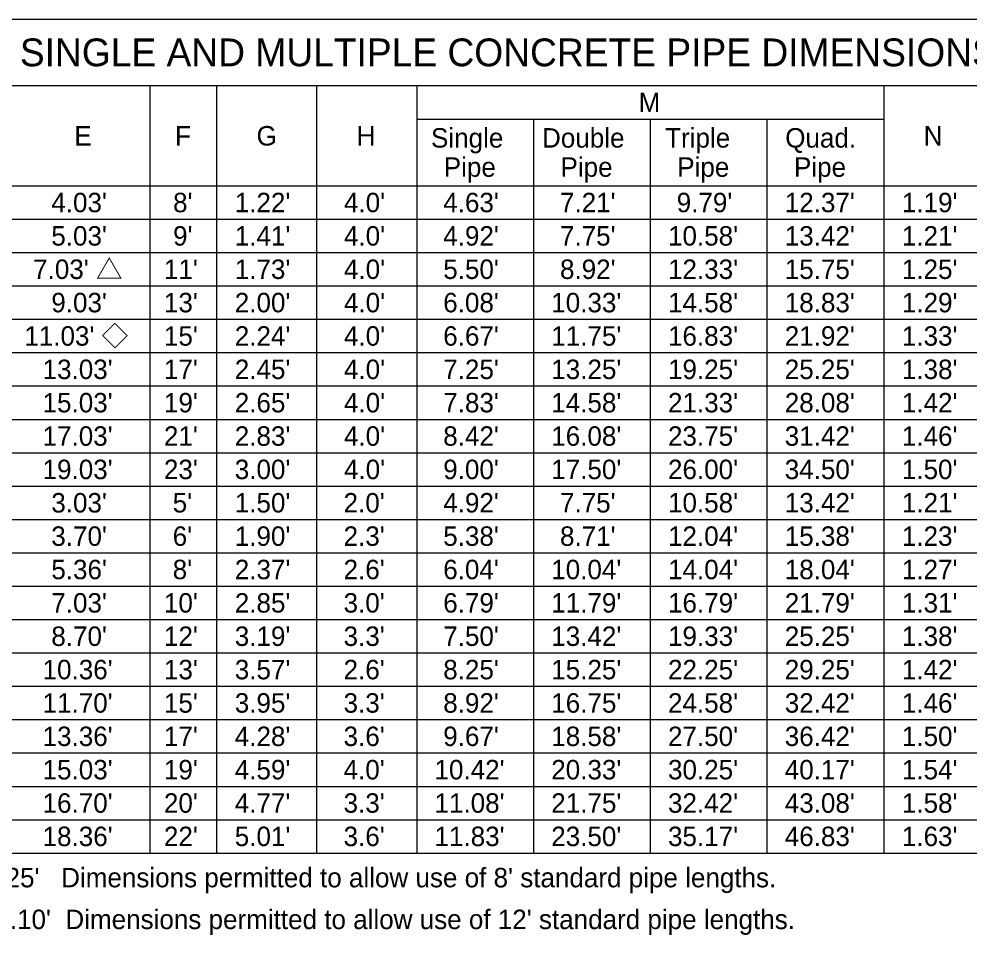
# Model space of a CAD drawing. Extents: x 2 to 14.5, y 0.1 to 8.2.
# Drawn here: x 4.889 to 8.31, y 4.933 to 8.227 of the extents above; entities that cross this region are included whole.
import ezdxf

# ---------------------------------------------------------------- set-up
doc = ezdxf.new("R2010")
doc.units = 0
doc.layers.add('TextNotes', color=7, linetype='Continuous')
doc.layers.add('TextTables', color=7, linetype='Continuous')

msp = doc.modelspace()

# ---------------------------------------------------------------- linework, layer by layer
at = {"layer": 'TextTables'}
msp.add_line((2, 8.2274), (13.4, 8.2274), dxfattribs=at)
for points in [[(13.4, 7.9874), (11.72, 7.9874), (10.04, 7.9874), (8.36, 7.9874), (8, 7.9874), (6.32, 7.9874), (5.96, 7.9874), (5.6, 7.9874), (5.36, 7.9874), (4.88, 7.9874), (4.46, 7.9874), (3.98, 7.9874), (3.56, 7.9874), (3.14, 7.9874), (2.84, 7.9874), (2.54, 7.9874), (2.24, 7.9874), (2, 7.9874)], [(5.36, 7.9874), (5.36, 7.6274), (5.36, 7.5074), (5.36, 7.3874), (5.36, 7.2674), (5.36, 7.1474), (5.36, 7.0274), (5.36, 6.9074), (5.36, 6.7874), (5.36, 6.6674), (5.36, 6.5474), (5.36, 6.4274), (5.36, 6.3074), (5.36, 6.1874), (5.36, 6.0674), (5.36, 5.9474), (5.36, 5.8274), (5.36, 5.7074), (5.36, 5.5874), (5.36, 5.4674), (5.36, 5.3474), (5.36, 5.2274)], [(5.6, 7.9874), (5.6, 7.6274), (5.6, 7.5074), (5.6, 7.3874), (5.6, 7.2674), (5.6, 7.1474), (5.6, 7.0274), (5.6, 6.9074), (5.6, 6.7874), (5.6, 6.6674), (5.6, 6.5474), (5.6, 6.4274), (5.6, 6.3074), (5.6, 6.1874), (5.6, 6.0674), (5.6, 5.9474), (5.6, 5.8274), (5.6, 5.7074), (5.6, 5.5874), (5.6, 5.4674), (5.6, 5.3474), (5.6, 5.2274)], [(5.96, 7.9874), (5.96, 7.6274), (5.96, 7.5074), (5.96, 7.3874), (5.96, 7.2674), (5.96, 7.1474), (5.96, 7.0274), (5.96, 6.9074), (5.96, 6.7874), (5.96, 6.6674), (5.96, 6.5474), (5.96, 6.4274), (5.96, 6.3074), (5.96, 6.1874), (5.96, 6.0674), (5.96, 5.9474), (5.96, 5.8274), (5.96, 5.7074), (5.96, 5.5874), (5.96, 5.4674), (5.96, 5.3474), (5.96, 5.2274)], [(6.32, 7.9874), (6.32, 7.8674), (6.32, 7.6274), (6.32, 7.5074), (6.32, 7.3874), (6.32, 7.2674), (6.32, 7.1474), (6.32, 7.0274), (6.32, 6.9074), (6.32, 6.7874), (6.32, 6.6674), (6.32, 6.5474), (6.32, 6.4274), (6.32, 6.3074), (6.32, 6.1874), (6.32, 6.0674), (6.32, 5.9474), (6.32, 5.8274), (6.32, 5.7074), (6.32, 5.5874), (6.32, 5.4674), (6.32, 5.3474), (6.32, 5.2274)], [(8, 7.9874), (8, 7.8674), (8, 7.6274), (8, 7.5074), (8, 7.3874), (8, 7.2674), (8, 7.1474), (8, 7.0274), (8, 6.9074), (8, 6.7874), (8, 6.6674), (8, 6.5474), (8, 6.4274), (8, 6.3074), (8, 6.1874), (8, 6.0674), (8, 5.9474), (8, 5.8274), (8, 5.7074), (8, 5.5874), (8, 5.4674), (8, 5.3474), (8, 5.2274)], [(6.32, 7.8674), (6.74, 7.8674), (7.16, 7.8674), (7.58, 7.8674), (8, 7.8674)], [(6.74, 7.8674), (6.74, 7.6274), (6.74, 7.5074), (6.74, 7.3874), (6.74, 7.2674), (6.74, 7.1474), (6.74, 7.0274), (6.74, 6.9074), (6.74, 6.7874), (6.74, 6.6674), (6.74, 6.5474), (6.74, 6.4274), (6.74, 6.3074), (6.74, 6.1874), (6.74, 6.0674), (6.74, 5.9474), (6.74, 5.8274), (6.74, 5.7074), (6.74, 5.5874), (6.74, 5.4674), (6.74, 5.3474), (6.74, 5.2274)], [(7.16, 7.8674), (7.16, 7.6274), (7.16, 7.5074), (7.16, 7.3874), (7.16, 7.2674), (7.16, 7.1474), (7.16, 7.0274), (7.16, 6.9074), (7.16, 6.7874), (7.16, 6.6674), (7.16, 6.5474), (7.16, 6.4274), (7.16, 6.3074), (7.16, 6.1874), (7.16, 6.0674), (7.16, 5.9474), (7.16, 5.8274), (7.16, 5.7074), (7.16, 5.5874), (7.16, 5.4674), (7.16, 5.3474), (7.16, 5.2274)], [(7.58, 7.8674), (7.58, 7.6274), (7.58, 7.5074), (7.58, 7.3874), (7.58, 7.2674), (7.58, 7.1474), (7.58, 7.0274), (7.58, 6.9074), (7.58, 6.7874), (7.58, 6.6674), (7.58, 6.5474), (7.58, 6.4274), (7.58, 6.3074), (7.58, 6.1874), (7.58, 6.0674), (7.58, 5.9474), (7.58, 5.8274), (7.58, 5.7074), (7.58, 5.5874), (7.58, 5.4674), (7.58, 5.3474), (7.58, 5.2274)], [(2, 7.6274), (2.24, 7.6274), (2.54, 7.6274), (2.84, 7.6274), (3.14, 7.6274), (3.56, 7.6274), (3.98, 7.6274), (4.46, 7.6274), (4.88, 7.6274), (5.36, 7.6274), (5.6, 7.6274), (5.96, 7.6274), (6.32, 7.6274), (6.74, 7.6274), (7.16, 7.6274), (7.58, 7.6274), (8, 7.6274), (8.36, 7.6274)], [(2.24, 7.5074), (2.54, 7.5074), (2.84, 7.5074), (3.14, 7.5074), (3.56, 7.5074), (3.98, 7.5074), (4.46, 7.5074), (4.88, 7.5074), (5.36, 7.5074), (5.6, 7.5074), (5.96, 7.5074), (6.32, 7.5074), (6.74, 7.5074), (7.16, 7.5074), (7.58, 7.5074), (8, 7.5074), (8.36, 7.5074)], [(2.24, 7.3874), (2.54, 7.3874), (2.84, 7.3874), (3.14, 7.3874), (3.56, 7.3874), (3.98, 7.3874), (4.46, 7.3874), (4.88, 7.3874), (5.36, 7.3874), (5.6, 7.3874), (5.96, 7.3874), (6.32, 7.3874), (6.74, 7.3874), (7.16, 7.3874), (7.58, 7.3874), (8, 7.3874), (8.36, 7.3874)], [(2.24, 7.2674), (2.54, 7.2674), (2.84, 7.2674), (3.14, 7.2674), (3.56, 7.2674), (3.98, 7.2674), (4.46, 7.2674), (4.88, 7.2674), (5.36, 7.2674), (5.6, 7.2674), (5.96, 7.2674), (6.32, 7.2674), (6.74, 7.2674), (7.16, 7.2674), (7.58, 7.2674), (8, 7.2674), (8.36, 7.2674)], [(2.24, 7.1474), (2.54, 7.1474), (2.84, 7.1474), (3.14, 7.1474), (3.56, 7.1474), (3.98, 7.1474), (4.46, 7.1474), (4.88, 7.1474), (5.36, 7.1474), (5.6, 7.1474), (5.96, 7.1474), (6.32, 7.1474), (6.74, 7.1474), (7.16, 7.1474), (7.58, 7.1474), (8, 7.1474), (8.36, 7.1474)], [(2.24, 7.0274), (2.54, 7.0274), (2.84, 7.0274), (3.14, 7.0274), (3.56, 7.0274), (3.98, 7.0274), (4.46, 7.0274), (4.88, 7.0274), (5.36, 7.0274), (5.6, 7.0274), (5.96, 7.0274), (6.32, 7.0274), (6.74, 7.0274), (7.16, 7.0274), (7.58, 7.0274), (8, 7.0274), (8.36, 7.0274)], [(2.24, 6.9074), (2.54, 6.9074), (2.84, 6.9074), (3.14, 6.9074), (3.56, 6.9074), (3.98, 6.9074), (4.46, 6.9074), (4.88, 6.9074), (5.36, 6.9074), (5.6, 6.9074), (5.96, 6.9074), (6.32, 6.9074), (6.74, 6.9074), (7.16, 6.9074), (7.58, 6.9074), (8, 6.9074), (8.36, 6.9074)], [(2.24, 6.7874), (2.54, 6.7874), (2.84, 6.7874), (3.14, 6.7874), (3.56, 6.7874), (3.98, 6.7874), (4.46, 6.7874), (4.88, 6.7874), (5.36, 6.7874), (5.6, 6.7874), (5.96, 6.7874), (6.32, 6.7874), (6.74, 6.7874), (7.16, 6.7874), (7.58, 6.7874), (8, 6.7874), (8.36, 6.7874)], [(2.24, 6.6674), (2.54, 6.6674), (2.84, 6.6674), (3.14, 6.6674), (3.56, 6.6674), (3.98, 6.6674), (4.46, 6.6674), (4.88, 6.6674), (5.36, 6.6674), (5.6, 6.6674), (5.96, 6.6674), (6.32, 6.6674), (6.74, 6.6674), (7.16, 6.6674), (7.58, 6.6674), (8, 6.6674), (8.36, 6.6674)], [(2, 6.5474), (2.24, 6.5474), (2.54, 6.5474), (2.84, 6.5474), (3.14, 6.5474), (3.56, 6.5474), (3.98, 6.5474), (4.46, 6.5474), (4.88, 6.5474), (5.36, 6.5474), (5.6, 6.5474), (5.96, 6.5474), (6.32, 6.5474), (6.74, 6.5474), (7.16, 6.5474), (7.58, 6.5474), (8, 6.5474), (8.36, 6.5474)], [(2.24, 6.4274), (2.54, 6.4274), (2.84, 6.4274), (3.14, 6.4274), (3.56, 6.4274), (3.98, 6.4274), (4.46, 6.4274), (4.88, 6.4274), (5.36, 6.4274), (5.6, 6.4274), (5.96, 6.4274), (6.32, 6.4274), (6.74, 6.4274), (7.16, 6.4274), (7.58, 6.4274), (8, 6.4274), (8.36, 6.4274)], [(2.24, 6.3074), (2.54, 6.3074), (2.84, 6.3074), (3.14, 6.3074), (3.56, 6.3074), (3.98, 6.3074), (4.46, 6.3074), (4.88, 6.3074), (5.36, 6.3074), (5.6, 6.3074), (5.96, 6.3074), (6.32, 6.3074), (6.74, 6.3074), (7.16, 6.3074), (7.58, 6.3074), (8, 6.3074), (8.36, 6.3074)], [(2.24, 6.1874), (2.54, 6.1874), (2.84, 6.1874), (3.14, 6.1874), (3.56, 6.1874), (3.98, 6.1874), (4.46, 6.1874), (4.88, 6.1874), (5.36, 6.1874), (5.6, 6.1874), (5.96, 6.1874), (6.32, 6.1874), (6.74, 6.1874), (7.16, 6.1874), (7.58, 6.1874), (8, 6.1874), (8.36, 6.1874)], [(2.24, 6.0674), (2.54, 6.0674), (2.84, 6.0674), (3.14, 6.0674), (3.56, 6.0674), (3.98, 6.0674), (4.46, 6.0674), (4.88, 6.0674), (5.36, 6.0674), (5.6, 6.0674), (5.96, 6.0674), (6.32, 6.0674), (6.74, 6.0674), (7.16, 6.0674), (7.58, 6.0674), (8, 6.0674), (8.36, 6.0674)], [(2.24, 5.9474), (2.54, 5.9474), (2.84, 5.9474), (3.14, 5.9474), (3.56, 5.9474), (3.98, 5.9474), (4.46, 5.9474), (4.88, 5.9474), (5.36, 5.9474), (5.6, 5.9474), (5.96, 5.9474), (6.32, 5.9474), (6.74, 5.9474), (7.16, 5.9474), (7.58, 5.9474), (8, 5.9474), (8.36, 5.9474)], [(2.24, 5.8274), (2.54, 5.8274), (2.84, 5.8274), (3.14, 5.8274), (3.56, 5.8274), (3.98, 5.8274), (4.46, 5.8274), (4.88, 5.8274), (5.36, 5.8274), (5.6, 5.8274), (5.96, 5.8274), (6.32, 5.8274), (6.74, 5.8274), (7.16, 5.8274), (7.58, 5.8274), (8, 5.8274), (8.36, 5.8274)], [(2.24, 5.7074), (2.54, 5.7074), (2.84, 5.7074), (3.14, 5.7074), (3.56, 5.7074), (3.98, 5.7074), (4.46, 5.7074), (4.88, 5.7074), (5.36, 5.7074), (5.6, 5.7074), (5.96, 5.7074), (6.32, 5.7074), (6.74, 5.7074), (7.16, 5.7074), (7.58, 5.7074), (8, 5.7074), (8.36, 5.7074)], [(2.24, 5.5874), (2.54, 5.5874), (2.84, 5.5874), (3.14, 5.5874), (3.56, 5.5874), (3.98, 5.5874), (4.46, 5.5874), (4.88, 5.5874), (5.36, 5.5874), (5.6, 5.5874), (5.96, 5.5874), (6.32, 5.5874), (6.74, 5.5874), (7.16, 5.5874), (7.58, 5.5874), (8, 5.5874), (8.36, 5.5874)], [(2.24, 5.4674), (2.54, 5.4674), (2.84, 5.4674), (3.14, 5.4674), (3.56, 5.4674), (3.98, 5.4674), (4.46, 5.4674), (4.88, 5.4674), (5.36, 5.4674), (5.6, 5.4674), (5.96, 5.4674), (6.32, 5.4674), (6.74, 5.4674), (7.16, 5.4674), (7.58, 5.4674), (8, 5.4674), (8.36, 5.4674)], [(2.24, 5.3474), (2.54, 5.3474), (2.84, 5.3474), (3.14, 5.3474), (3.56, 5.3474), (3.98, 5.3474), (4.46, 5.3474), (4.88, 5.3474), (5.36, 5.3474), (5.6, 5.3474), (5.96, 5.3474), (6.32, 5.3474), (6.74, 5.3474), (7.16, 5.3474), (7.58, 5.3474), (8, 5.3474), (8.36, 5.3474)], [(2, 5.2274), (2.24, 5.2274), (2.54, 5.2274), (2.84, 5.2274), (3.14, 5.2274), (3.56, 5.2274), (3.98, 5.2274), (4.46, 5.2274), (4.88, 5.2274), (5.36, 5.2274), (5.6, 5.2274), (5.96, 5.2274), (6.32, 5.2274), (6.74, 5.2274), (7.16, 5.2274), (7.58, 5.2274), (8, 5.2274), (8.36, 5.2274)]]:
    msp.add_lwpolyline(points, dxfattribs=at)

# ---------------------------------------------------------------- texts
at = {"layer": 'TextNotes'}
for s, height, p in [('SINGLE AND MULTIPLE CONCRETE PIPE DIMENSIONS AND QUANTITIES', 0.1, (4.8923, 8.0574)), ('M', 0.07, (7.1183, 7.8924)), ('E', 0.07, (5.0882, 7.7724)), ('F', 0.07, (5.4503, 7.7724)), ('G', 0.07, (5.7438, 7.7724)), ('H', 0.07, (6.1037, 7.7724)), ('Single', 0.07, (6.3714, 7.7649)), ('Double', 0.07, (6.7709, 7.7649)), ('Triple', 0.07, (7.2137, 7.7649)), ('Quad.', 0.07, (7.6457, 7.7649)), ('N', 0.07, (8.1438, 7.7724)), ('Pipe', 0.07, (6.4173, 7.6599)), ('Pipe', 0.07, (6.8373, 7.6599)), ('Pipe', 0.07, (7.2573, 7.6599)), ('Pipe', 0.07, (7.6773, 7.6599))]:
    msp.add_text(s, height=height, dxfattribs=at).set_placement(p)
for s, p in [("4.03'", (5.0054, 7.5324)), (" 8'", (5.4175, 7.5324)), ("1.22'", (5.6654, 7.5324)), (" 4.0'", (6.0323, 7.5324)), ("4.63'", (6.4154, 7.5324)), ("7.21'", (6.8354, 7.5324)), ("9.79'", (7.2554, 7.5324)), ("12.37'", (7.644, 7.5324)), ("1.19'", (8.0654, 7.5324)), ("5.03'", (5.0054, 7.4124)), (" 9'", (5.4175, 7.4124)), ("1.41'", (5.6654, 7.4124)), (" 4.0'", (6.0323, 7.4124)), ("4.92'", (6.4154, 7.4124)), ("7.75'", (6.8354, 7.4124)), ("10.58'", (7.224, 7.4124)), ("13.42'", (7.644, 7.4124)), ("1.21'", (8.0654, 7.4124)), ("7.03' △", (4.94, 7.2924)), ("11'", (5.4106, 7.2924)), ("1.73'", (5.6654, 7.2924)), (" 4.0'", (6.0323, 7.2924)), ("5.50'", (6.4154, 7.2924)), ("8.92'", (6.8354, 7.2924)), ("12.33'", (7.224, 7.2924)), ("15.75'", (7.644, 7.2924)), ("1.25'", (8.0654, 7.2924)), ("9.03'", (5.0054, 7.1724)), ("13'", (5.4106, 7.1724)), ("2.00'", (5.6654, 7.1724)), (" 4.0'", (6.0323, 7.1724)), ("6.08'", (6.4154, 7.1724)), ("10.33'", (6.804, 7.1724)), ("14.58'", (7.224, 7.1724)), ("18.83'", (7.644, 7.1724)), ("1.29'", (8.0654, 7.1724)), ("11.03' ◇", (4.9083, 7.0524)), ("15'", (5.4106, 7.0524)), ("2.24'", (5.6654, 7.0524)), (" 4.0'", (6.0323, 7.0524)), ("6.67'", (6.4154, 7.0524)), ("11.75'", (6.804, 7.0524)), ("16.83'", (7.224, 7.0524)), ("21.92'", (7.644, 7.0524)), ("1.33'", (8.0654, 7.0524)), ("13.03'", (4.974, 6.9324)), ("17'", (5.4106, 6.9324)), ("2.45'", (5.6654, 6.9324)), (" 4.0'", (6.0323, 6.9324)), ("7.25'", (6.4154, 6.9324)), ("13.25'", (6.804, 6.9324)), ("19.25'", (7.224, 6.9324)), ("25.25'", (7.644, 6.9324)), ("1.38'", (8.0654, 6.9324)), ("15.03'", (4.974, 6.8124)), ("19'", (5.4106, 6.8124)), ("2.65'", (5.6654, 6.8124)), (" 4.0'", (6.0323, 6.8124)), ("7.83'", (6.4154, 6.8124)), ("14.58'", (6.804, 6.8124)), ("21.33'", (7.224, 6.8124)), ("28.08'", (7.644, 6.8124)), ("1.42'", (8.0654, 6.8124)), ("17.03'", (4.974, 6.6924)), ("21'", (5.4106, 6.6924)), ("2.83'", (5.6654, 6.6924)), (" 4.0'", (6.0323, 6.6924)), ("8.42'", (6.4154, 6.6924)), ("16.08'", (6.804, 6.6924)), ("23.75'", (7.224, 6.6924)), ("31.42'", (7.644, 6.6924)), ("1.46'", (8.0654, 6.6924)), ("19.03'", (4.974, 6.5724)), ("23'", (5.4106, 6.5724)), ("3.00'", (5.6654, 6.5724)), (" 4.0'", (6.0323, 6.5724)), ("9.00'", (6.4154, 6.5724)), ("17.50'", (6.804, 6.5724)), ("26.00'", (7.224, 6.5724)), ("34.50'", (7.644, 6.5724)), ("1.50'", (8.0654, 6.5724)), ("3.03'", (5.0054, 6.4524)), ("5'", (5.4421, 6.4524)), ("1.50'", (5.6654, 6.4524)), ("2.0'", (6.0569, 6.4524)), ("4.92'", (6.4154, 6.4524)), ("7.75'", (6.8354, 6.4524)), ("10.58'", (7.224, 6.4524)), ("13.42'", (7.644, 6.4524)), ("1.21'", (8.0654, 6.4524)), ("3.70'", (5.0054, 6.3324)), ("6'", (5.4421, 6.3324)), ("1.90'", (5.6654, 6.3324)), ("2.3'", (6.0569, 6.3324)), ("5.38'", (6.4154, 6.3324)), ("8.71'", (6.8354, 6.3324)), ("12.04'", (7.224, 6.3324)), ("15.38'", (7.644, 6.3324)), ("1.23'", (8.0654, 6.3324)), ("5.36'", (5.0054, 6.2124)), ("8'", (5.4421, 6.2124)), ("2.37'", (5.6654, 6.2124)), ("2.6'", (6.0569, 6.2124)), ("6.04'", (6.4154, 6.2124)), ("10.04'", (6.804, 6.2124)), ("14.04'", (7.224, 6.2124)), ("18.04'", (7.644, 6.2124)), ("1.27'", (8.0654, 6.2124)), ("7.03'", (5.0054, 6.0924)), ("10'", (5.4106, 6.0924)), ("2.85'", (5.6654, 6.0924)), ("3.0'", (6.0569, 6.0924)), ("6.79'", (6.4154, 6.0924)), ("11.79'", (6.804, 6.0924)), ("16.79'", (7.224, 6.0924)), ("21.79'", (7.644, 6.0924)), ("1.31'", (8.0654, 6.0924)), ("8.70'", (5.0054, 5.9724)), ("12'", (5.4106, 5.9724)), ("3.19'", (5.6654, 5.9724)), ("3.3'", (6.0569, 5.9724)), ("7.50'", (6.4154, 5.9724)), ("13.42'", (6.804, 5.9724)), ("19.33'", (7.224, 5.9724)), ("25.25'", (7.644, 5.9724)), ("1.38'", (8.0654, 5.9724)), ("10.36'", (4.974, 5.8524)), ("13'", (5.4106, 5.8524)), ("3.57'", (5.6654, 5.8524)), ("2.6'", (6.0569, 5.8524)), ("8.25'", (6.4154, 5.8524)), ("15.25'", (6.804, 5.8524)), ("22.25'", (7.224, 5.8524)), ("29.25'", (7.644, 5.8524)), ("1.42'", (8.0654, 5.8524)), ("11.70'", (4.974, 5.7324)), ("15'", (5.4106, 5.7324)), ("3.95'", (5.6654, 5.7324)), ("3.3'", (6.0569, 5.7324)), ("8.92'", (6.4154, 5.7324)), ("16.75'", (6.804, 5.7324)), ("24.58'", (7.224, 5.7324)), ("32.42'", (7.644, 5.7324)), ("1.46'", (8.0654, 5.7324)), ("13.36'", (4.974, 5.6124)), ("17'", (5.4106, 5.6124)), ("4.28'", (5.6654, 5.6124)), ("3.6'", (6.0569, 5.6124)), ("9.67'", (6.4154, 5.6124)), ("18.58'", (6.804, 5.6124)), ("27.50'", (7.224, 5.6124)), ("36.42'", (7.644, 5.6124)), ("1.50'", (8.0654, 5.6124)), ("15.03'", (4.974, 5.4924)), ("19'", (5.4106, 5.4924)), ("4.59'", (5.6654, 5.4924)), ("4.0'", (6.0569, 5.4924)), ("10.42'", (6.384, 5.4924)), ("20.33'", (6.804, 5.4924)), ("30.25'", (7.224, 5.4924)), ("40.17'", (7.644, 5.4924)), ("1.54'", (8.0654, 5.4924)), ("16.70'", (4.974, 5.3724)), ("20'", (5.4106, 5.3724)), ("4.77'", (5.6654, 5.3724)), ("3.3'", (6.0569, 5.3724)), ("11.08'", (6.384, 5.3724)), ("21.75'", (6.804, 5.3724)), ("32.42'", (7.224, 5.3724)), ("43.08'", (7.644, 5.3724)), ("1.58'", (8.0654, 5.3724)), ("18.36'", (4.974, 5.2524)), ("22'", (5.4106, 5.2524)), ("5.01'", (5.6654, 5.2524)), ("3.6'", (6.0569, 5.2524)), ("11.83'", (6.384, 5.2524)), ("23.50'", (6.804, 5.2524)), ("35.17'", (7.224, 5.2524)), ("46.83'", (7.644, 5.2524)), ("1.63'", (8.0654, 5.2524)), ("△6.42'            △6.25'   Dimensions permitted to allow use of 8' standard pipe lengths.", (4.0597, 5.1042)), ("◇10.40'           ◇10.10'  Dimensions permitted to allow use of 12' standard pipe lengths.", (4.0228, 4.9539))]:
    msp.add_text(s, height=0.07, rotation=0, dxfattribs=at).set_placement(p)

doc.saveas('drawing.dxf')
